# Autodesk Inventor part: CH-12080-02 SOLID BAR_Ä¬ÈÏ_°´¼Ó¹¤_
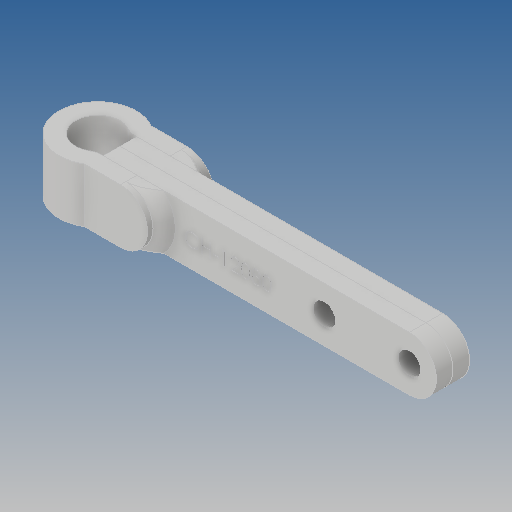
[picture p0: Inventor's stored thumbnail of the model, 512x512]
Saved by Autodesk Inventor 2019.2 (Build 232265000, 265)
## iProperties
Created: 2015-08
Part Number: CH-12080-02 SOLID BAR_Ä¬ÈÏ_°´¼Ó¹¤_
Material: Ogólny
Document SubType Name: Modeling
Designer: CADENGINEERING4
Density: 1 g/cm^3
Appearance: Domyślna
Author: CADENGINEERING4
Revision Number: ÈÎºÎ
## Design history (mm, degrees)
feature "Ô²½Ç1"
feature "Ô²½Çº¸·ì1"
feature "Ô²½Çº¸·ì2"
feature "À­Éì3"
feature "À­Éì6"
node "Bryła1"
node "Bryła2"
node "Bryła3"
node "Bryła4"
node "Bryła5"
